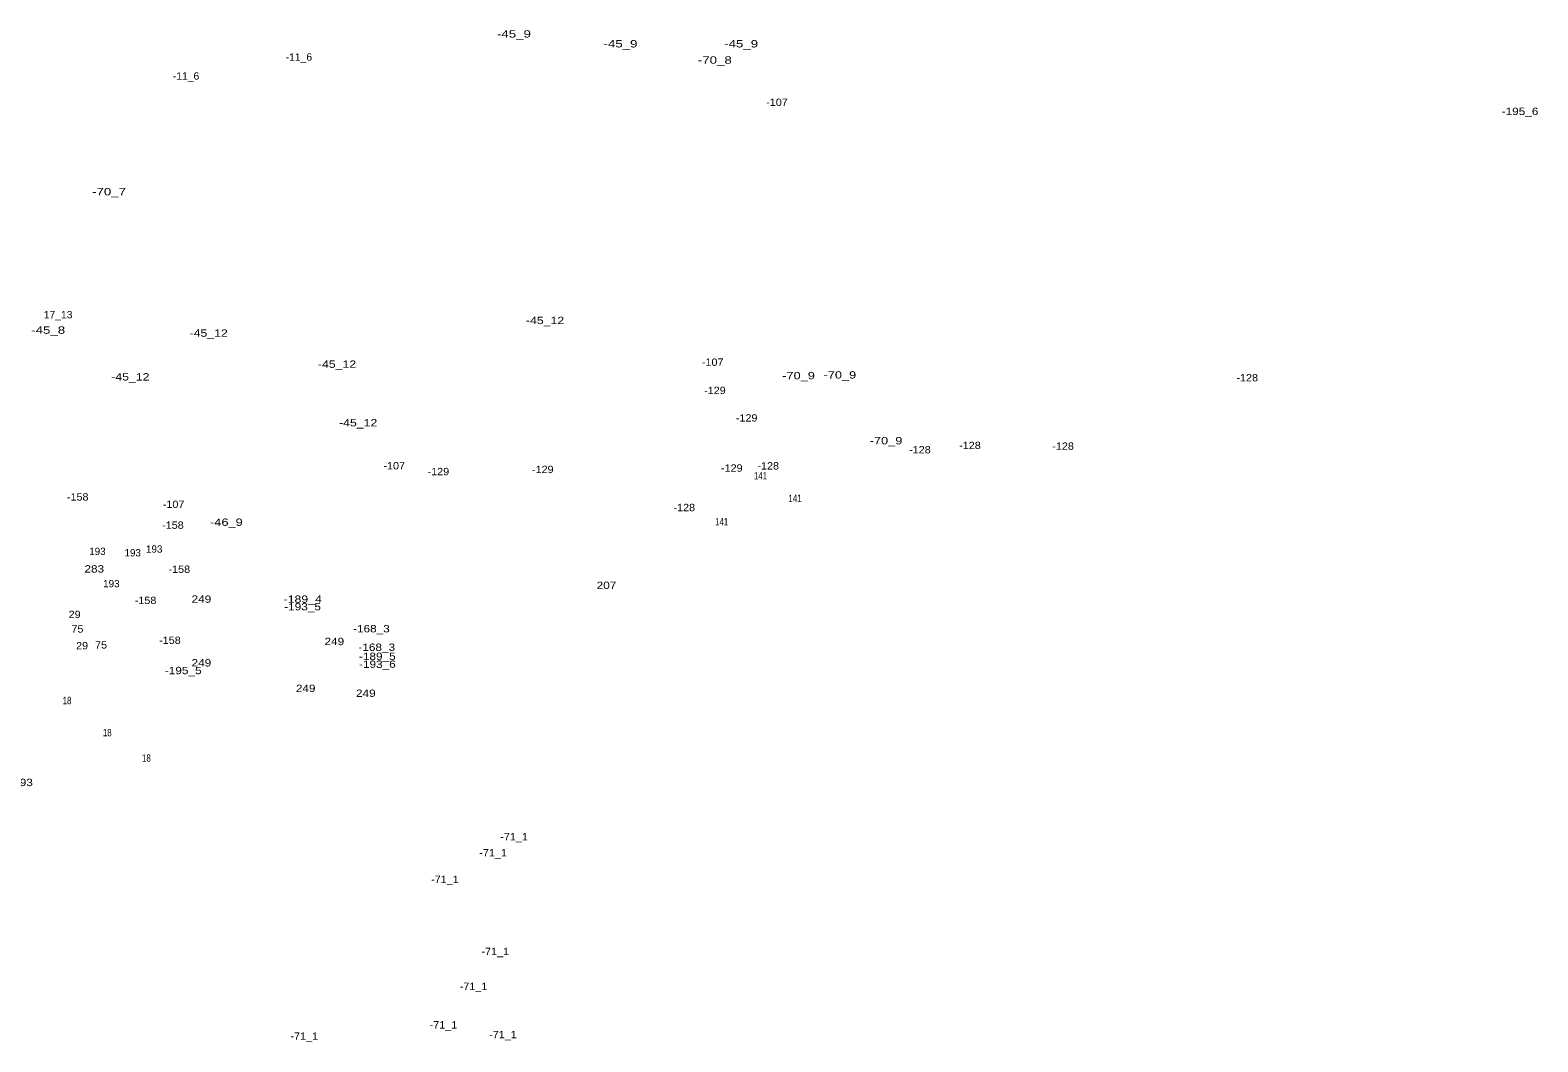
# Model space of a CAD drawing. Extents: x -662996 to -659766, y -998554 to -993949.
# Drawn here: x -660587 to -659766, y -997968 to -997417 of the extents above; entities that cross this region are included whole.
import ezdxf
from ezdxf.enums import TextEntityAlignment as Align

# ---------------------------------------------------------------- set-up
doc = ezdxf.new("R2010")
doc.units = 0
doc.header["$LTSCALE"] = 1.6
doc.layers.add('24', color=7, linetype='Continuous')

msp = doc.modelspace()

# ---------------------------------------------------------------- texts
at = {"layer": '24'}
for s, width, p in [('-45_9', 1.35, (-660323.7, -997420.87)), ('-45_9', 1.35, (-660265.71, -997426.24)), ('-45_9', 1.35, (-660200.04, -997426.24)), ('-11_6', 1.05, (-660440.75, -997433.41)), ('-70_8', 1.35, (-660214.36, -997435.07)), ('-11_6', 1.05, (-660502.191, -997443.78)), ('-107', 1.1, (-660180.53, -997458.06)), ('-195_6', 1.2, (-659776.06, -997463.03)), ('-70_7', 1.35, (-660544.111, -997506.76)), ('17_13', 1.05, (-660571.83, -997573.74)), ('-45_8', 1.35, (-660577.23, -997582.14)), ('-45_12', 1.25, (-660306.76, -997576.86)), ('-45_12', 1.25, (-660489.9, -997583.77)), ('-45_12', 1.25, (-660420.01, -997600.68)), ('-107', 1.1, (-660215.52, -997599.59)), ('-70_9', 1.3, (-660168.77, -997606.9)), ('-70_9', 1.3, (-660146.3, -997606.52)), ('-45_12', 1.25, (-660532.52, -997607.59)), ('-129', 1.1, (-660214.32, -997614.98)), ('-128', 1.1, (-659924.551, -997608.04)), ('-129', 1.1, (-660197.04, -997629.96)), ('-45_12', 1.25, (-660408.49, -997632.56)), ('-70_9', 1.3, (-660121.16, -997642.33)), ('-128', 1.1, (-660102.731, -997647.23)), ('-128', 1.1, (-660075.471, -997644.92)), ('-128', 1.1, (-660024.78, -997645.31)), ('-107', 1.1, (-660388.87, -997655.97)), ('-128', 1.1, (-660185.301, -997656.06)), ('-129', 1.1, (-660364.85, -997659.16)), ('-129', 1.1, (-660308.02, -997658)), ('-129', 1.1, (-660205.1, -997657.24)), ('141', 0.8, (-660189.52, -997661.48)), ('-158', 1.1, (-660561.171, -997672.97)), ('-107', 1.1, (-660508.97, -997676.96)), ('-128', 1.1, (-660230.99, -997678.73)), ('141', 0.8, (-660170.699, -997673.77)), ('-158', 1.1, (-660509.331, -997688.33)), ('-46_9', 1.3, (-660480.221, -997686.72)), ('141', 0.8, (-660210.64, -997686.45)), ('283', 1.2, (-660552.14, -997712.16)), ('-158', 1.1, (-660505.87, -997712.34)), ('207', 1.2, (-660273.32, -997721.09)), ('-158', 1.1, (-660524.231, -997729.31)), ('249', 1.2, (-660493.83, -997728.62)), ('-189_4', 1.25, (-660438.69, -997728.62)), ('29', 1.1, (-660562.83, -997736.96)), ('-193_5', 1.2, (-660438.76, -997732.74)), ('75', 1.1, (-660561.34, -997744.85)), ('-168_3', 1.2, (-660401.291, -997744.72)), ('29', 1.1, (-660558.79, -997753.96)), ('75', 1.1, (-660548.47, -997753.55)), ('-158', 1.1, (-660510.981, -997751.02)), ('249', 1.2, (-660421.47, -997751.67)), ('-168_3', 1.2, (-660398.39, -997754.81)), ('-189_5', 1.2, (-660398.071, -997759.77)), ('-195_5', 1.2, (-660503.74, -997767.49)), ('249', 1.2, (-660493.83, -997763.29)), ('-193_6', 1.2, (-660398.04, -997764.04)), ('249', 1.2, (-660437.08, -997777.19)), ('18', 0.8, (-660566.97, -997783.82)), ('249', 1.2, (-660404.33, -997779.86)), ('18', 0.8, (-660545.079, -997801.3)), ('18', 0.8, (-660523.77, -997815.13)), ('-93', 1.2, (-660590.2, -997828.44)), ('-71_1', 1.1, (-660323.601, -997857.94)), ('-71_1', 1.1, (-660335.03, -997866.7)), ('-71_1', 1.1, (-660361.301, -997881.18)), ('-71_1', 1.1, (-660333.88, -997920.42)), ('-71_1', 1.1, (-660345.691, -997939.46)), ('-71_1', 1.1, (-660437.851, -997966.53)), ('-71_1', 1.1, (-660362.061, -997960.42)), ('-71_1', 1.1, (-660329.691, -997965.71))]:
    msp.add_text(s, height=4, dxfattribs=dict(at, width=width)).set_placement(p, align=Align.CENTER)
for p in [(-660550.431, -997702.6), (-660531.231, -997703.37), (-660519.52, -997701.35), (-660542.851, -997720.17)]:
    msp.add_text('193', height=4, dxfattribs=at).set_placement(p, align=Align.CENTER)

doc.saveas('drawing.dxf')
